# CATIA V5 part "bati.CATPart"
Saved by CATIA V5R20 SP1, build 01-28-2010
Part number: bati
Bounding box of the stored display mesh (mm): x -48.897 to 51.07, y -30 to 0, z -28.649 to 57.239
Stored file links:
  C:\Users\Matthieu\Desktop\IAO_2012_mcamard_Catia\bati.CATPart
  C:\Users\Matthieu\Desktop\IAO_Artobolevsky\Artobolevsky_786.CATProduct
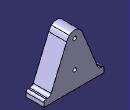
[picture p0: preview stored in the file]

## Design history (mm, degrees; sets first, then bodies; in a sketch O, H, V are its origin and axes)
Parameters
  epaisseur_bati = 30 mm
Set1
  Point1 "A": linked copy from another document
Body1 (main body)
  Sketch1 on zx-plane, origin (0, 0, 0), H (-1, 0, 0), V (0, 0, 1)
    line L1 (-13.3611, 46.6645) -> (-39.246, -14.562)
    line L2 (-45.1409, -18.4698) -> (-47.5697, -18.4698)
    line L3 (-51.0697, -21.9698) -> (-51.0697, -28.6489)
    line L4 (-51.0697, -28.6489) -> (48.8968, -28.6489)
    line L5 (48.8968, -28.6489) -> (48.8968, -21.9698)
    point P3 (48.8968, -18.4698)
    line L6 (45.3968, -18.4698) -> (44.2804, -18.4698)
    line L7 (38.3561, -14.491) -> (13.4625, 46.4204)
    line L8 (8.654, 53.654) -> (8.654, 53.654)
    point P4 (0, 62.3079)
    line L9 (-8.654, 53.654) -> (-8.654, 53.654)
    arc A1 centre (-6.9024, 38.0976) radius 22 from (8.654, 53.654) to (13.4625, 46.4204) cw
    point P5 (8.654, 53.654)
    arc A2 centre (6.9024, 38.0976) radius 22 from (-13.3611, 46.6645) to (-8.654, 53.654) cw
    point P9 (-8.654, 53.654)
    arc A3 centre (-45.1409, -12.0698) radius 6.4 from (-45.1409, -18.4698) to (-39.246, -14.562) ccw
    arc A4 centre (44.2804, -12.0698) radius 6.4 from (44.2804, -18.4698) to (38.3561, -14.491) cw
    arc A5 centre (45.3968, -21.9698) radius 3.5 from (45.3968, -18.4698) to (48.8968, -21.9698) cw
    arc A6 centre (-47.5697, -21.9698) radius 3.5 from (-47.5697, -18.4698) to (-51.0697, -21.9698) ccw
    arc A7 centre (0, 45) radius 12.2385 from (-8.654, 53.654) to (8.654, 53.654) cw
    point P23 (-8.654, 53.654)
    point P24 (8.654, 53.654)
    point P25 (0, 45)
    circle A8 centre (0, 45) radius 3
    reference projected point E1 (0, 45) from Point1
    circle A9 centre (0, 0) radius 3
    radius A1 = 22
    radius A2 = 22
    radius A3 = 6.4
    radius A4 = 6.4
    radius A5 = 3.5
    radius A6 = 3.5
    radius A7 = 12.2385
    distance P5 P24 = 0
    distance P9 P23 = 0
    distance P25 E1 = 0
    horizontal: L2 H, L4 H, L6 H
    vertical: L3 V, L5 V
    coincidence: P3 L2, P4 V, L6 P3, L5 P3, L9 P4, L8 P4
    perpendicularity: L9 L8
    tangency: A1 L8, A1 L7, A2 L1, A2 L9, A3 L2, A3 L1, A4 L6, A4 L7, A5 L6, A5 L5, A6 L2, A6 L3, A7 L9, A7 L8
  Pad1: profile Sketch1, direction (0, -1, 0), length 30 {= epaisseur_bati}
